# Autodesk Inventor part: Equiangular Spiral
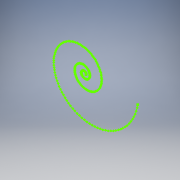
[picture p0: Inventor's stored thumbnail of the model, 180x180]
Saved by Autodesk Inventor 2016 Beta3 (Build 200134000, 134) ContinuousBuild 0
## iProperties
Created: 2008-02
Part Number: Equiangular Spiral
Document SubType Name: Modeling
Designer: Autodesk, Inc.
Density: 1 g/cm^3
Material: Generic
Appearance: Default
Author: Autodesk, Inc.
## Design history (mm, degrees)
sketch "Sketch1"
  geometry: 301 further points
  constraints: 301 other
